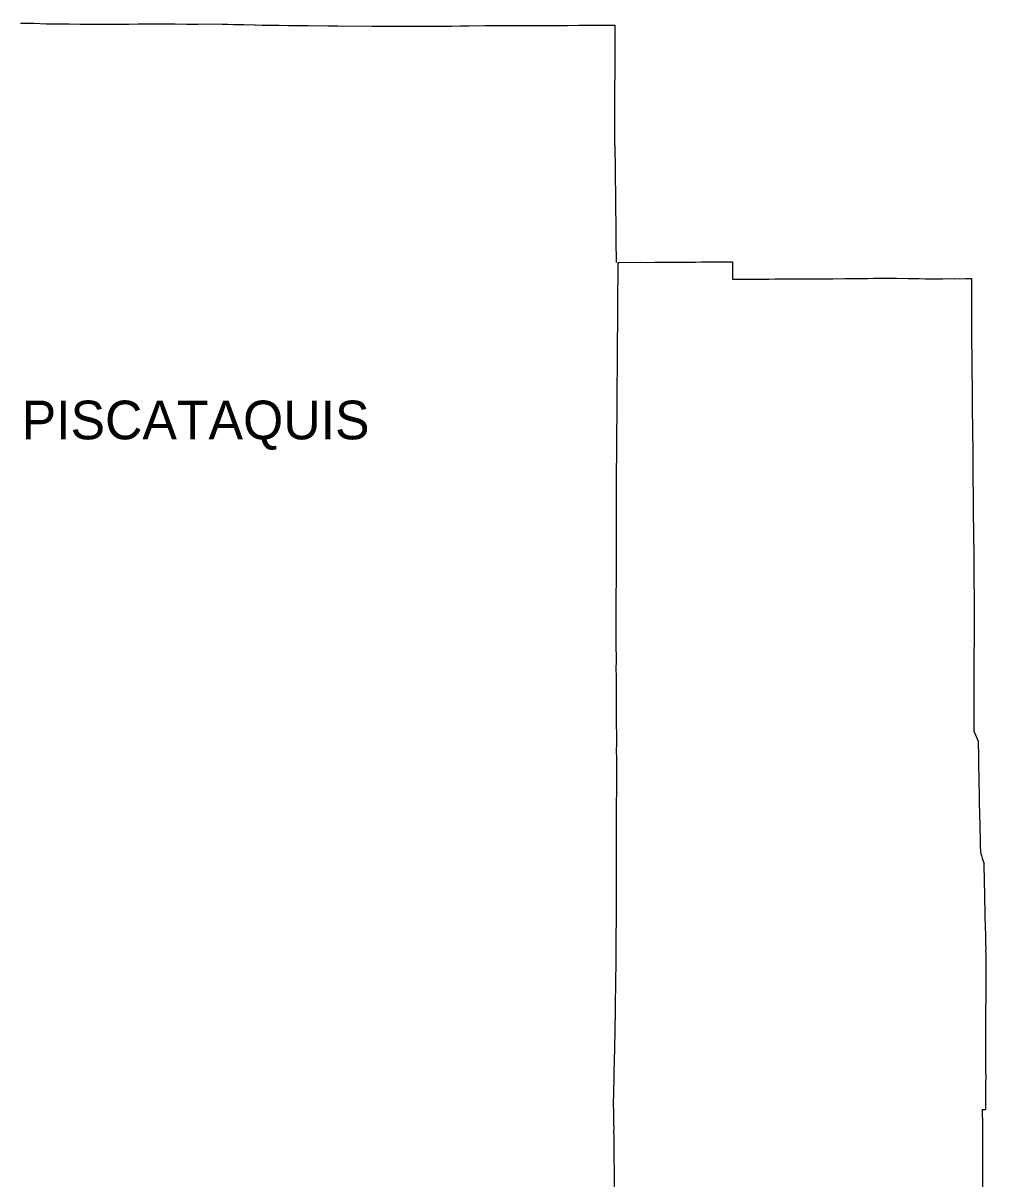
# Model space of a CAD drawing. Extents: x 1104458 to 2179854, y 15641624 to 17244911.
# Drawn here: x 1523774 to 1786548, y 16606552 to 16922100 of the extents above; entities that cross this region are included whole.
import ezdxf

# ---------------------------------------------------------------- set-up
doc = ezdxf.new("R2010")
doc.units = 0
doc.layers.add('ANNOTATION', color=7, linetype='Continuous')
doc.layers.add('CO BORDER', color=7, linetype='Continuous')

msp = doc.modelspace()

# ---------------------------------------------------------------- linework, layer by layer
at = {"layer": 'CO BORDER'}
for points in [[(1523013, 16922100), (1523821, 16922100), (1526728, 16922044), (1530126, 16921949), (1533616, 16921924), (1536332, 16921895), (1539381, 16921855), (1542871, 16921786), (1546095, 16921786), (1549153, 16921829), (1552586, 16921845), (1555214, 16921865)], [(1555214, 16921865), (1555877, 16921868), (1558585, 16921908), (1562533, 16921878), (1565316, 16921882), (1568490, 16921849), (1571455, 16921832), (1574847, 16921891), (1578087, 16921839), (1579536, 16921829), (1581203, 16921757), (1584109, 16921701), (1586891, 16921596), (1587079, 16921596)], [(1587079, 16921596), (1588999, 16921573), (1591099, 16921567), (1593647, 16921511), (1596213, 16921493), (1598404, 16921470), (1601577, 16921411), (1606967, 16921378), (1609674, 16921332), (1619066, 16921270)], [(1619066, 16921270), (1620754, 16921263), (1622603, 16921283), (1625695, 16921266), (1628577, 16921270), (1634652, 16921240), (1636713, 16921266), (1638421, 16921263), (1640703, 16921296), (1643134, 16921355), (1645466, 16921381), (1649896, 16921407), (1652968, 16921417)], [(1652968, 16921417), (1655059, 16921421), (1656924, 16921434), (1661355, 16921417), (1663320, 16921430), (1666284, 16921429), (1669990, 16921481), (1672388, 16921491), (1675461, 16921530), (1679167, 16921514), (1681856, 16921534), (1683905, 16921524), (1685383, 16921530)], [(1685254, 16888656), (1685250, 16889348), (1685275, 16892590), (1685309, 16894030), (1685315, 16894942), (1685313, 16896376), (1685296, 16898610), (1685298, 16901766), (1685329, 16911215), (1685364, 16913355), (1685344, 16914923), (1685364, 16917938), (1685360, 16919588), (1685383, 16921530)], [(1685254, 16888656), (1685259, 16887839), (1685287, 16886231), (1685331, 16884414), (1685361, 16882189), (1685400, 16879896), (1685427, 16875513), (1685478, 16872704), (1685476, 16870345), (1685512, 16868511), (1685518, 16866297), (1685561, 16862104), (1685623, 16857504), (1685653, 16856779)], [(1686054, 16856772), (1686074, 16855939), (1686074, 16854571), (1685990, 16846621), (1685977, 16844646), (1685982, 16842586), (1685962, 16840388), (1685958, 16838403), (1685942, 16836969), (1685936, 16833928), (1685889, 16830709), (1685877, 16828609), (1685873, 16826710), (1685821, 16824357), (1685821, 16823967)], [(1686054, 16856772), (1686476, 16856766), (1688333, 16856795), (1691498, 16856782), (1692679, 16856805), (1694004, 16856779), (1696185, 16856812), (1697801, 16856795), (1699283, 16856822), (1701006, 16856831), (1702988, 16856828), (1704121, 16856861), (1705719, 16856871), (1707260, 16856854), (1708800, 16856881), (1710407, 16856881), (1711906, 16856917), (1713579, 16856894), (1715478, 16856887), (1716660, 16856904), (1717385, 16856894)], [(1717385, 16856894), (1717389, 16856182), (1717412, 16855234), (1717428, 16853951), (1717398, 16852176)], [(1717398, 16852176), (1718189, 16852163), (1719662, 16852196), (1722402, 16852196), (1724184, 16852209), (1727290, 16852212), (1729013, 16852255), (1730521, 16852248), (1732219, 16852284), (1733726, 16852284), (1735058, 16852310), (1736948, 16852287), (1738256, 16852312), (1740013, 16852309), (1741778, 16852328), (1743360, 16852302), (1744767, 16852296), (1748114, 16852342), (1749499, 16852368)], [(1749499, 16852368), (1750762, 16852365), (1752894, 16852378), (1754409, 16852414), (1755899, 16852430), (1757640, 16852466), (1759105, 16852433), (1760562, 16852470), (1762178, 16852463), (1765359, 16852374), (1768382, 16852342), (1769997, 16852309), (1771521, 16852302), (1773153, 16852322), (1774760, 16852315), (1777900, 16852335), (1779465, 16852328), (1781064, 16852338), (1782255, 16852368), (1782617, 16852355)], [(1782617, 16852355), (1782624, 16851764), (1782628, 16849838), (1782620, 16848470), (1782644, 16847237), (1782616, 16846429), (1782630, 16844146), (1782617, 16840904), (1782619, 16839362), (1782628, 16837860), (1782648, 16836045), (1782649, 16834369), (1782699, 16831836), (1782758, 16827669), (1782746, 16825593), (1782774, 16823860), (1782811, 16820533)], [(1685821, 16823967), (1685825, 16822317), (1685799, 16819758), (1685777, 16816641), (1685786, 16813931), (1685768, 16811388), (1685711, 16808481), (1685724, 16806388), (1685693, 16804620), (1685696, 16802854), (1685682, 16801178), (1685681, 16798586), (1685652, 16793986), (1685645, 16790961)], [(1782811, 16820533), (1782837, 16817702), (1782837, 16815084), (1782858, 16812958), (1782896, 16810960), (1782899, 16808949), (1782946, 16806859), (1782975, 16803483), (1782985, 16800576), (1782980, 16798798), (1782994, 16796491), (1783057, 16794391), (1783123, 16789175), (1783121, 16788735)], [(1685645, 16790961), (1685647, 16789367), (1685636, 16787067), (1685644, 16784436), (1685622, 16781260), (1685622, 16778648), (1685601, 16776673), (1685620, 16773566), (1685619, 16773240)], [(1783121, 16788735), (1783114, 16786573), (1783166, 16784824), (1783168, 16783213), (1783192, 16780664), (1783238, 16778765), (1783235, 16776504), (1783255, 16774555), (1783251, 16772521), (1783280, 16769253), (1783317, 16765946), (1783322, 16763830), (1783363, 16761238), (1783349, 16759562), (1783356, 16758448)], [(1685619, 16773240), (1685614, 16771866), (1685603, 16769606), (1685566, 16766207), (1685522, 16763979), (1685549, 16762198), (1685567, 16758356)], [(1685567, 16758356), (1685570, 16757637), (1685548, 16754511), (1685551, 16752686), (1685596, 16748119), (1685586, 16745754), (1685631, 16743887), (1685627, 16741718), (1685640, 16739753), (1685633, 16736827), (1685655, 16734625), (1685659, 16732525), (1685657, 16730252), (1685711, 16728218), (1685733, 16726033), (1685723, 16725491)], [(1783356, 16758448), (1783351, 16756614), (1783313, 16753336), (1783292, 16750068), (1783261, 16746961), (1783252, 16744520), (1783273, 16742384), (1783269, 16740409), (1783231, 16737135), (1783221, 16730701), (1783228, 16729609), (1783224, 16728900), (1783376, 16728585), (1783722, 16727768), (1784482, 16726049)], [(1685723, 16725491), (1685683, 16723359), (1685702, 16721567), (1685711, 16719976), (1685722, 16715708), (1685719, 16714025), (1685698, 16712666), (1685710, 16711633), (1685682, 16709900), (1685669, 16706807), (1685657, 16705773), (1685658, 16703686), (1685684, 16702213), (1685657, 16700327), (1685679, 16699152), (1685652, 16697285), (1685662, 16695835), (1685641, 16694116), (1685637, 16693142)], [(1784482, 16726049), (1784525, 16721915), (1784531, 16719809), (1784617, 16715609), (1784625, 16714048), (1784696, 16712378), (1784744, 16710494), (1784758, 16709310), (1784749, 16708011), (1784782, 16707368), (1784823, 16705993), (1784867, 16703102), (1784906, 16701928), (1784959, 16699694), (1784972, 16698575), (1785000, 16697719), (1785033, 16696977), (1785039, 16696492), (1785036, 16696068), (1785056, 16695875), (1785049, 16695734), (1785136, 16695425), (1785351, 16694805), (1785560, 16694113), (1785741, 16693575), (1785853, 16693319), (1785931, 16693060), (1785965, 16693020)], [(1685637, 16693142), (1685663, 16693017), (1685683, 16692043), (1685672, 16690875), (1685647, 16689549), (1685650, 16687948), (1685664, 16686780), (1685655, 16685471), (1685667, 16684447), (1685666, 16681855), (1685626, 16680363), (1685636, 16678145), (1685627, 16676819), (1685562, 16673276), (1685563, 16671865), (1685546, 16668430), (1685551, 16666672), (1685534, 16665362), (1685520, 16663761), (1685489, 16662246), (1685445, 16661019), (1685469, 16660444)], [(1785965, 16693020), (1785982, 16692302), (1785994, 16691344), (1786056, 16688909), (1786067, 16688010), (1786106, 16686928), (1786147, 16684917), (1786176, 16683952), (1786152, 16683119), (1786185, 16682443), (1786194, 16681777), (1786231, 16680727), (1786245, 16679657), (1786306, 16677367), (1786320, 16676166), (1786365, 16675258), (1786363, 16674749), (1786400, 16673709), (1786416, 16672400), (1786462, 16671416), (1786481, 16670533), (1786493, 16669565), (1786478, 16668689), (1786496, 16667905), (1786496, 16667206), (1786505, 16666481), (1786508, 16665572), (1786528, 16664631), (1786532, 16663555), (1786548, 16662272), (1786529, 16660421), (1786539, 16659680)], [(1685469, 16660444), (1685434, 16659900), (1685436, 16659034), (1685384, 16655090), (1685384, 16653748), (1685352, 16652272), (1685367, 16651714), (1685359, 16651032), (1685334, 16650379), (1685346, 16650038), (1685325, 16649903)], [(1786539, 16659680), (1786511, 16658519), (1786516, 16657377), (1786515, 16655477), (1786487, 16653000), (1786489, 16652118), (1786467, 16651199), (1786487, 16648181), (1786480, 16646032), (1786450, 16645064), (1786474, 16640379), (1786453, 16637954), (1786481, 16636435), (1786494, 16634001), (1786470, 16633210), (1786447, 16631008), (1786457, 16629489), (1786423, 16628190), (1786405, 16626907), (1786417, 16625989), (1786431, 16625497)], [(1685325, 16649903), (1685315, 16649837), (1685251, 16647587), (1685230, 16646543), (1685234, 16645553), (1685190, 16643751), (1685189, 16642465), (1685139, 16641025), (1685111, 16639982), (1685089, 16639030), (1685070, 16637829), (1685027, 16636586), (1685011, 16634519), (1684989, 16633535), (1684984, 16632619), (1684929, 16631668), (1684923, 16629417), (1684862, 16627563), (1684863, 16626855), (1684850, 16626546), (1684856, 16626031)], [(1684856, 16626031), (1684876, 16625805), (1684879, 16624821), (1684903, 16623564), (1684916, 16622455), (1684946, 16621346), (1684958, 16620372), (1684954, 16619345), (1684994, 16618088), (1684987, 16617311), (1685036, 16614046), (1685029, 16612527), (1685030, 16611103), (1685048, 16609643), (1685070, 16608485), (1685070, 16607842), (1685100, 16606700), (1685124, 16605434), (1685130, 16603534), (1685152, 16601782), (1685159, 16600526), (1685179, 16599541), (1685175, 16598574), (1685193, 16597757)], [(1785548, 16625497), (1785989, 16625516), (1786431, 16625497)], [(1785548, 16625497), (1785552, 16624453), (1785582, 16622061), (1785592, 16618508), (1785601, 16617019), (1785608, 16613751), (1785598, 16612524), (1785621, 16610598), (1785629, 16609315), (1785620, 16605939), (1785599, 16604204), (1785628, 16601828), (1785622, 16600978), (1785593, 16599961), (1785608, 16598679), (1785605, 16597642), (1785618, 16596510), (1785604, 16595007), (1785614, 16594184), (1785600, 16593232), (1785583, 16592573), (1785596, 16592215)]]:
    msp.add_lwpolyline(points, dxfattribs=at)

# ---------------------------------------------------------------- texts
at = {"layer": 'ANNOTATION'}
msp.add_text('PISCATAQUIS', height=10560.16, dxfattribs=at).set_placement((1523377, 16808467))

doc.saveas('drawing.dxf')
